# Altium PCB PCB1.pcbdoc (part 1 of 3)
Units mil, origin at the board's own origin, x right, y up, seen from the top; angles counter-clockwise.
Board outline 8664.15 x 6684.89 mil, 2 copper layers (Top Layer, Bottom Layer); 317 components, 306 nets, 1008 pads, 181 vias.
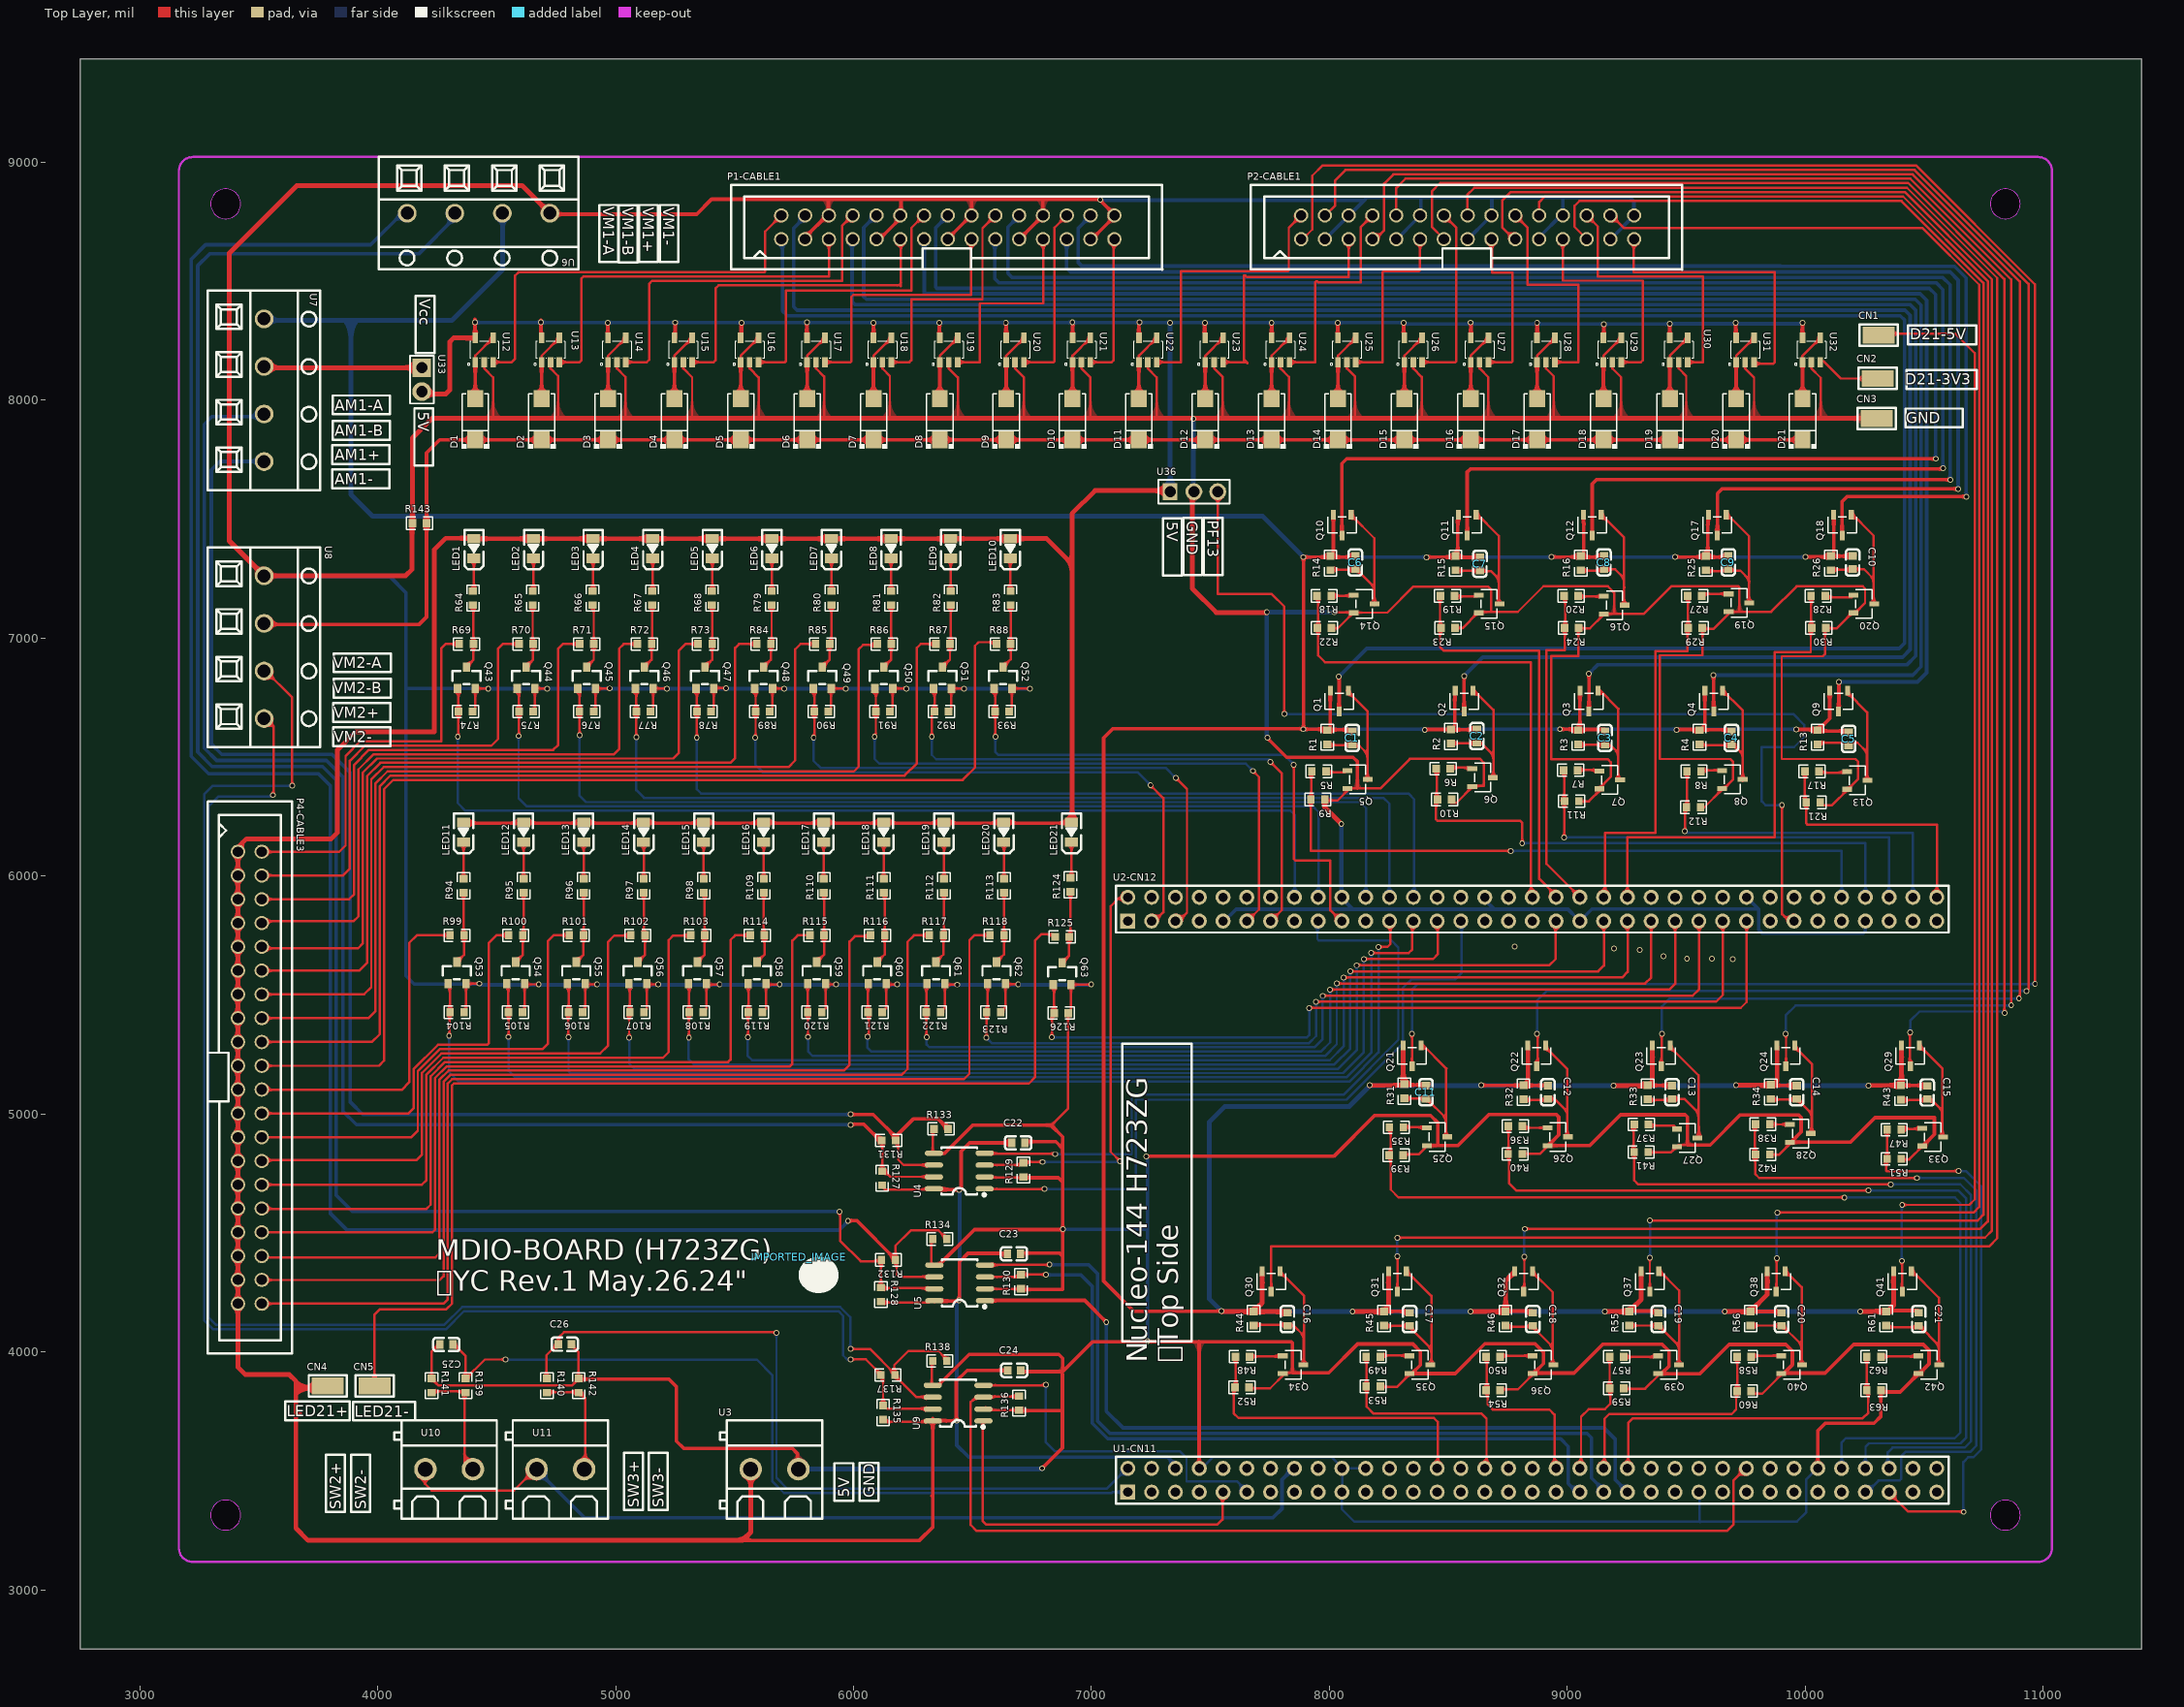
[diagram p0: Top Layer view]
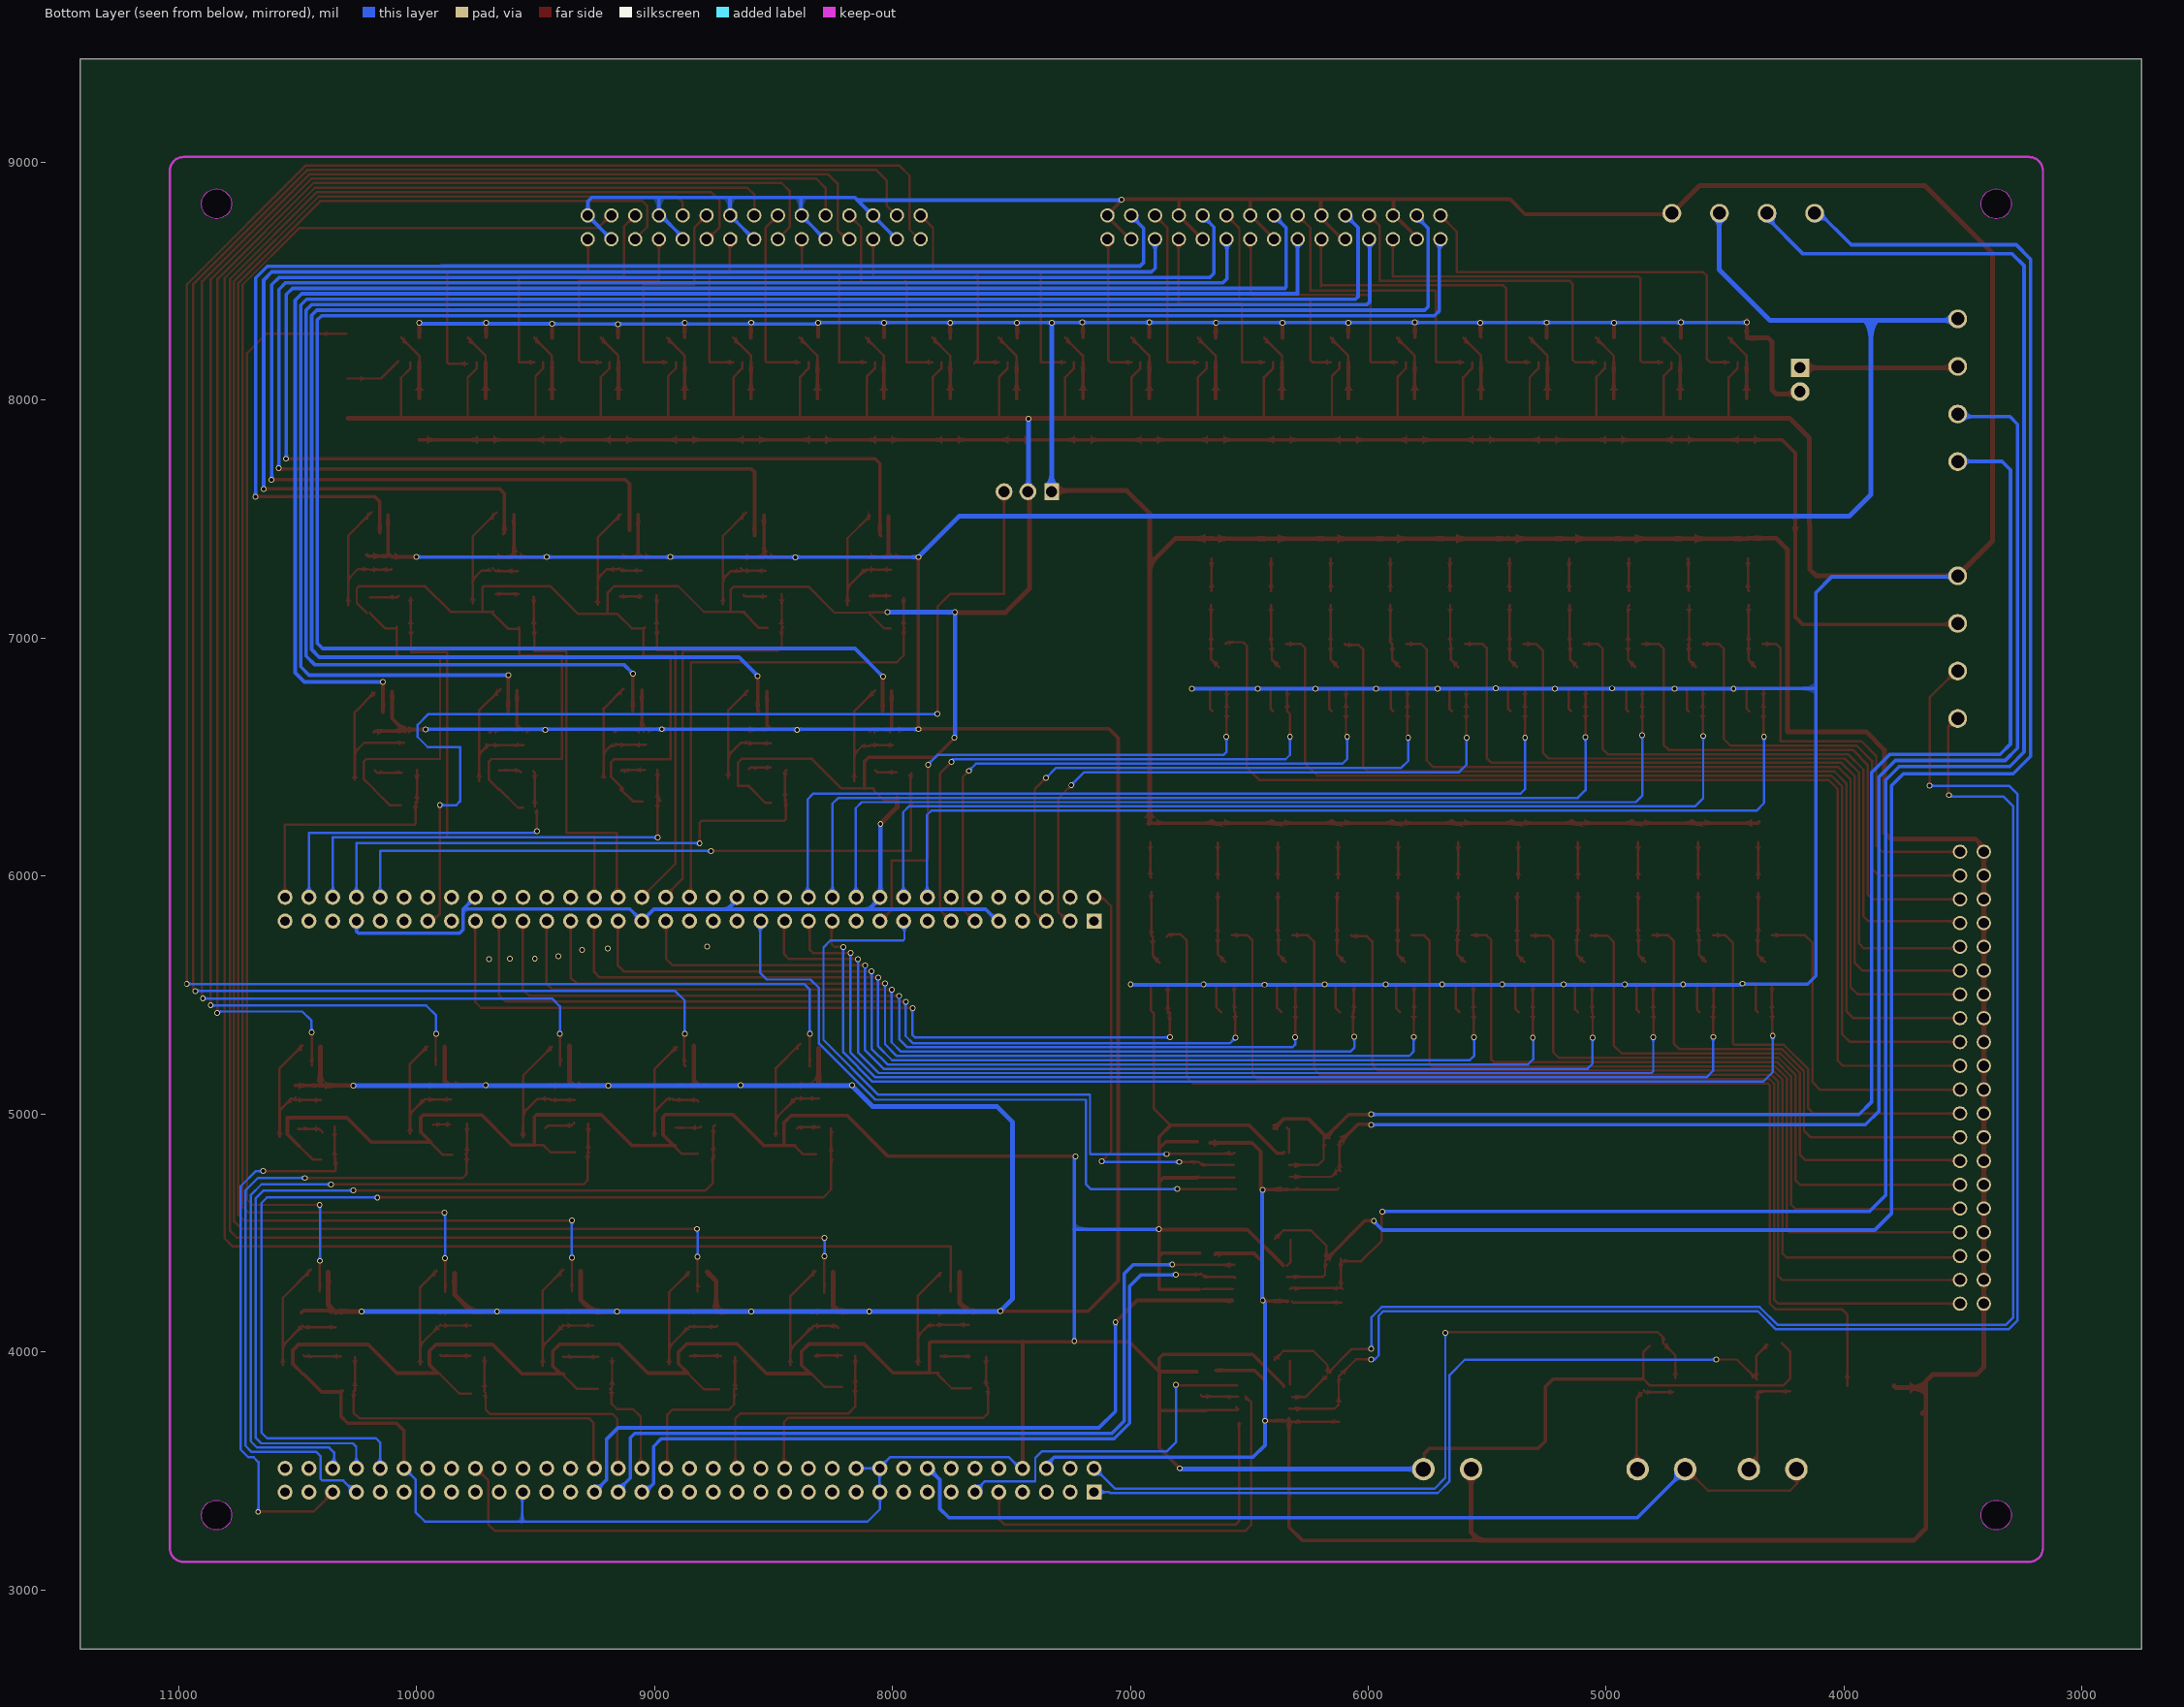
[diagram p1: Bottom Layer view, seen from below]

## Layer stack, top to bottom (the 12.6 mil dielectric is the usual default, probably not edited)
Top Layer: signal copper (thickness not stored)
Dielectric: dielectric 12.6, FR-4, Dk 4.8
Bottom Layer: signal copper (thickness not stored)

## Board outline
11414.15,2750 2750,2750 2750,9434.89 11414.15,9434.89
cut-out: 3424.16,8825.83 ccw(c3361.16,8825.83) 3298.17,8825.83 ccw(c3361.16,8825.83)
cut-out: 10904.47,8825.83 ccw(c10841.48,8825.57) 10778.49,8825.83 ccw(c10841.48,8826.1)
cut-out: 3424.16,3314.02 ccw(c3361.16,3314.02) 3298.17,3314.02 ccw(c3361.16,3314.02)
cut-out: 10904.47,3314.02 ccw(c10841.48,3313.76) 10778.49,3314.02 ccw(c10841.48,3314.28)

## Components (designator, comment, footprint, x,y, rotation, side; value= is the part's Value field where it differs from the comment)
C1 "CC0603KRX7R9BB104" C0603 8096.46,6580.71 r270 top
C2 "CC0603KRX7R9BB104" C0603 8620.56,6588.58 r270 top
C3 "CC0603KRX7R9BB104" C0603 9158.6,6580.71 r270 top
C4 "CC0603KRX7R9BB104" C0603 9690.58,6580.71 r270 top
C5 "CC0603KRX7R9BB104" C0603 10183.18,6576.77 r270 top
C6 "CC0603KRX7R9BB104" C0603 8109.33,7317.96 r270 top
C7 "CC0603KRX7R9BB104" C0603 8633.08,7312.76 r270 top
C8 "CC0603KRX7R9BB104" C0603 9154.54,7318.74 r270 top
C9 "CC0603KRX7R9BB104" C0603 9677.15,7318.74 r270 top
C10 "CC0603KRX7R9BB104" C0603 10199.75,7317.96 r270 top
C11 "CC0603KRX7R9BB104" C0603 8406.25,5091.19 r270 top
C12 "CC0603KRX7R9BB104" C0603 8918.53,5091.19 r270 top
C13 "CC0603KRX7R9BB104" C0603 9440.51,5091.19 r270 top
C14 "CC0603KRX7R9BB104" C0603 9964.56,5091.19 r270 top
C15 "CC0603KRX7R9BB104" C0603 10513.35,5090.23 r270 top
C16 "CC0603KRX7R9BB104" C0603 7824.05,4137.39 r270 top
C17 "CC0603KRX7R9BB104" C0603 8337.81,4137.39 r270 top
C18 "CC0603KRX7R9BB104" C0603 8855.53,4137.39 r270 top
C19 "CC0603KRX7R9BB104" C0603 9383.25,4137.39 r270 top
C20 "CC0603KRX7R9BB104" C0603 9900.97,4137.39 r270 top
C21 "CC0603KRX7R9BB104" C0603 10477.74,4137.39 r270 top
C22 "CC0603KRX7R9BB104" C0603 6692.77,4878.39 r0 top
C23 "CC0603KRX7R9BB104" C0603 6674.79,4412.07 r0 top
C24 "CC0603KRX7R9BB104" C0603 6676.02,3922.29 r0 top
C25 "CC0603KRX7R9BB104" C0603 4288.48,4031.19 r180 top
C26 "CC0603KRX7R9BB104" C0603 4786.68,4032.37 r0 top
CN1 "5017" CONN-SMD_5017 10309.01,8273.69 r0 top
CN2 "5017" CONN-SMD_5017 10305.08,8091.8 r0 top
CN3 "5017" CONN-SMD_5017 10301.14,7923.29 r0 top
CN4 "5017" CONN-SMD_5017 3790.3,3857.33 r0 top
CN5 "5017" CONN-SMD_5017 3987.15,3857.33 r0 top
D1 "B360A-13-F" SMA_L4.4-W2.6-LS5.0-RD 4410.46,7920.32 r90 top
D2 "B360A-13-F" SMA_L4.4-W2.6-LS5.0-RD 4689.39,7920.32 r90 top
D3 "B360A-13-F" SMA_L4.4-W2.6-LS5.0-RD 4968.33,7920.32 r90 top
D4 "B360A-13-F" SMA_L4.4-W2.6-LS5.0-RD 5247.27,7920.32 r90 top
D5 "B360A-13-F" SMA_L4.4-W2.6-LS5.0-RD 5526.2,7920.32 r90 top
D6 "B360A-13-F" SMA_L4.4-W2.6-LS5.0-RD 5805.14,7920.32 r90 top
D7 "B360A-13-F" SMA_L4.4-W2.6-LS5.0-RD 6084.08,7920.32 r90 top
D8 "B360A-13-F" SMA_L4.4-W2.6-LS5.0-RD 6363.02,7920.32 r90 top
D9 "B360A-13-F" SMA_L4.4-W2.6-LS5.0-RD 6641.95,7920.32 r90 top
D10 "B360A-13-F" SMA_L4.4-W2.6-LS5.0-RD 6920.89,7920.32 r90 top
D11 "B360A-13-F" SMA_L4.4-W2.6-LS5.0-RD 7199.83,7920.32 r90 top
D12 "B360A-13-F" SMA_L4.4-W2.6-LS5.0-RD 7478.76,7920.32 r90 top
D13 "B360A-13-F" SMA_L4.4-W2.6-LS5.0-RD 7757.7,7920.32 r90 top
D14 "B360A-13-F" SMA_L4.4-W2.6-LS5.0-RD 8036.64,7920.32 r90 top
D15 "B360A-13-F" SMA_L4.4-W2.6-LS5.0-RD 8315.58,7920.32 r90 top
D16 "B360A-13-F" SMA_L4.4-W2.6-LS5.0-RD 8594.51,7920.32 r90 top
D17 "B360A-13-F" SMA_L4.4-W2.6-LS5.0-RD 8873.45,7920.32 r90 top
D18 "B360A-13-F" SMA_L4.4-W2.6-LS5.0-RD 9152.39,7920.32 r90 top
D19 "B360A-13-F" SMA_L4.4-W2.6-LS5.0-RD 9431.32,7920.32 r90 top
D20 "B360A-13-F" SMA_L4.4-W2.6-LS5.0-RD 9710.26,7920.32 r90 top
D21 "B360A-13-F" SMA_L4.4-W2.6-LS5.0-RD 9989.2,7920.32 r90 top
IMPORTED_IMAGE "IMPORTED_IMAGE" IMPORTED_IMAGE 5770.23,4398.28 r0 top
LED1 "SZYY0805YG" LED0805-R-RD_GREEN 4404.46,7377.01 r90 top
LED2 "SZYY0805YG" LED0805-R-RD_GREEN 4654.99,7377.01 r90 top
LED3 "SZYY0805YG" LED0805-R-RD_GREEN 4905.51,7377.01 r90 top
LED4 "SZYY0805YG" LED0805-R-RD_GREEN 5156.04,7377.01 r90 top
LED5 "SZYY0805YG" LED0805-R-RD_GREEN 5406.56,7377.01 r90 top
LED6 "SZYY0805YG" LED0805-R-RD_GREEN 5657.09,7377.01 r90 top
LED7 "SZYY0805YG" LED0805-R-RD_GREEN 5907.61,7377.01 r90 top
LED8 "SZYY0805YG" LED0805-R-RD_GREEN 6158.14,7377.01 r90 top
LED9 "SZYY0805YG" LED0805-R-RD_GREEN 6408.66,7377.01 r90 top
LED10 "SZYY0805YG" LED0805-R-RD_GREEN 6659.19,7377.01 r90 top
LED11 "SZYY0805YG" LED0805-R-RD_GREEN 4361.16,6184.1 r90 top
LED12 "SZYY0805YG" LED0805-R-RD_GREEN 4613.43,6184.1 r90 top
LED13 "SZYY0805YG" LED0805-R-RD_GREEN 4865.71,6184.1 r90 top
LED14 "SZYY0805YG" LED0805-R-RD_GREEN 5117.98,6184.1 r90 top
LED15 "SZYY0805YG" LED0805-R-RD_GREEN 5370.25,6184.1 r90 top
LED16 "SZYY0805YG" LED0805-R-RD_GREEN 5622.53,6184.1 r90 top
LED17 "SZYY0805YG" LED0805-R-RD_GREEN 5874.8,6184.1 r90 top
LED18 "SZYY0805YG" LED0805-R-RD_GREEN 6127.08,6184.1 r90 top
LED19 "SZYY0805YG" LED0805-R-RD_GREEN 6379.35,6184.1 r90 top
LED20 "SZYY0805YG" LED0805-R-RD_GREEN 6631.63,6184.1 r90 top
LED21 "SZYY0805YG" LED0805-R-RD_GREEN 6916.28,6184.1 r90 top
P1-CABLE1 "2.54-2*15P简牛" IDC-TH_30P-P2.54-V-R2-C15-S2.54 6396.6,8727.41 r0 top
P2-CABLE1 "2.54-2*15P简牛" IDC-TH_30P-P2.54-V-R2-C15-S2.54 8581.63,8727.4 r0 top
P4-CABLE3 "2.54-2*20P直简牛" IDC-TH_40P-P2.54_C9138 3462.95,5152.6 r270 top
Q1 "SI2301CDS-T1-GE3" SOT-23-3_L3.0-W1.7-P0.95-LS2.9-BR 8042.27,6735.28 r90 top
Q2 "SI2301CDS-T1-GE3" SOT-23-3_L3.0-W1.7-P0.95-LS2.9-BR 8566.88,6735.28 r90 top
Q3 "SI2301CDS-T1-GE3" SOT-23-3_L3.0-W1.7-P0.95-LS2.9-BR 9091.48,6735.28 r90 top
Q4 "SI2301CDS-T1-GE3" SOT-23-3_L3.0-W1.7-P0.95-LS2.9-BR 9616.09,6735.28 r90 top
Q5 "S8050 J3Y_C2146" SOT-23-3_L3.0-W1.7-P0.95-LS2.9-BR 8119.11,6406.06 r180 top
Q6 "S8050 J3Y_C2146" SOT-23-3_L3.0-W1.7-P0.95-LS2.9-BR 8644.19,6413.93 r180 top
Q7 "S8050 J3Y_C2146" SOT-23-3_L3.0-W1.7-P0.95-LS2.9-BR 9178.89,6404.14 r180 top
Q8 "S8050 J3Y_C2146" SOT-23-3_L3.0-W1.7-P0.95-LS2.9-BR 9694.36,6406.06 r180 top
Q9 "SI2301CDS-T1-GE3" SOT-23-3_L3.0-W1.7-P0.95-LS2.9-BR 10140.7,6735.28 r90 top
Q10 "SI2301CDS-T1-GE3" SOT-23-3_L3.0-W1.7-P0.95-LS2.9-BR 8054.08,7475.44 r90 top
Q11 "SI2301CDS-T1-GE3" SOT-23-3_L3.0-W1.7-P0.95-LS2.9-BR 8579.67,7475.44 r90 top
Q12 "SI2301CDS-T1-GE3" SOT-23-3_L3.0-W1.7-P0.95-LS2.9-BR 9105.26,7475.44 r90 top
Q13 "S8050 J3Y_C2146" SOT-23-3_L3.0-W1.7-P0.95-LS2.9-BR 10219.44,6402.12 r180 top
Q14 "S8050 J3Y_C2146" SOT-23-3_L3.0-W1.7-P0.95-LS2.9-BR 8146.67,7144.09 r180 top
Q15 "S8050 J3Y_C2146" SOT-23-3_L3.0-W1.7-P0.95-LS2.9-BR 8671.75,7144.09 r180 top
Q16 "S8050 J3Y_C2146" SOT-23-3_L3.0-W1.7-P0.95-LS2.9-BR 9198.11,7138.96 r180 top
Q17 "SI2301CDS-T1-GE3" SOT-23-3_L3.0-W1.7-P0.95-LS2.9-BR 9630.85,7475.44 r90 top
Q18 "SI2301CDS-T1-GE3" SOT-23-3_L3.0-W1.7-P0.95-LS2.9-BR 10156.45,7475.44 r90 top
Q19 "S8050 J3Y_C2146" SOT-23-3_L3.0-W1.7-P0.95-LS2.9-BR 9721.91,7148.67 r180 top
Q20 "S8050 J3Y_C2146" SOT-23-3_L3.0-W1.7-P0.95-LS2.9-BR 10247,7144.09 r180 top
Q21 "SI2301CDS-T1-GE3" SOT-23-3_L3.0-W1.7-P0.95-LS2.9-BR 8347.97,5244.4 r90 top
Q22 "SI2301CDS-T1-GE3" SOT-23-3_L3.0-W1.7-P0.95-LS2.9-BR 8871.59,5244.4 r90 top
Q23 "SI2301CDS-T1-GE3" SOT-23-3_L3.0-W1.7-P0.95-LS2.9-BR 9395.22,5244.4 r90 top
Q24 "SI2301CDS-T1-GE3" SOT-23-3_L3.0-W1.7-P0.95-LS2.9-BR 9918.84,5244.4 r90 top
Q25 "S8050 J3Y_C2146" SOT-23-3_L3.0-W1.7-P0.95-LS2.9-BR 8453.31,4903.93 r180 top
Q26 "S8050 J3Y_C2146" SOT-23-3_L3.0-W1.7-P0.95-LS2.9-BR 8960.72,4903.93 r180 top
Q27 "S8050 J3Y_C2146" SOT-23-3_L3.0-W1.7-P0.95-LS2.9-BR 9504.61,4899.14 r180 top
Q28 "S8050 J3Y_C2146" SOT-23-3_L3.0-W1.7-P0.95-LS2.9-BR 9980.51,4918.34 r180 top
Q29 "SI2301CDS-T1-GE3" SOT-23-3_L3.0-W1.7-P0.95-LS2.9-BR 10442.46,5244.4 r90 top
Q30 "SI2301CDS-T1-GE3" SOT-23-3_L3.0-W1.7-P0.95-LS2.9-BR 7755.56,4295.86 r90 top
Q31 "SI2301CDS-T1-GE3" SOT-23-3_L3.0-W1.7-P0.95-LS2.9-BR 8286.27,4295.86 r90 top
Q32 "SI2301CDS-T1-GE3" SOT-23-3_L3.0-W1.7-P0.95-LS2.9-BR 8816.98,4295.86 r90 top
Q33 "S8050 J3Y_C2146" SOT-23-3_L3.0-W1.7-P0.95-LS2.9-BR 10536.47,4902.96 r180 top
Q34 "S8050 J3Y_C2146" SOT-23-3_L3.0-W1.7-P0.95-LS2.9-BR 7847.68,3945.79 r180 top
Q35 "S8050 J3Y_C2146" SOT-23-3_L3.0-W1.7-P0.95-LS2.9-BR 8380.98,3945.79 r180 top
Q36 "S8050 J3Y_C2146" SOT-23-3_L3.0-W1.7-P0.95-LS2.9-BR 8898.48,3945.79 r180 top
Q37 "SI2301CDS-T1-GE3" SOT-23-3_L3.0-W1.7-P0.95-LS2.9-BR 9347.69,4295.86 r90 top
Q38 "SI2301CDS-T1-GE3" SOT-23-3_L3.0-W1.7-P0.95-LS2.9-BR 9878.4,4295.86 r90 top
Q39 "S8050 J3Y_C2146" SOT-23-3_L3.0-W1.7-P0.95-LS2.9-BR 9425.98,3945.79 r180 top
Q40 "S8050 J3Y_C2146" SOT-23-3_L3.0-W1.7-P0.95-LS2.9-BR 9943.48,3945.79 r180 top
Q41 "SI2301CDS-T1-GE3" SOT-23-3_L3.0-W1.7-P0.95-LS2.9-BR 10409.11,4295.86 r90 top
Q42 "S8050 J3Y_C2146" SOT-23-3_L3.0-W1.7-P0.95-LS2.9-BR 10520.04,3945.79 r180 top
Q43 "Si2302CDS-T1-GE3" SOT-23_L2.9-W1.3-P1.90-LS2.4-BR 4372.97,6833.7 r270 top
Q44 "Si2302CDS-T1-GE3" SOT-23_L2.9-W1.3-P1.90-LS2.4-BR 4623.62,6833.7 r270 top
Q45 "Si2302CDS-T1-GE3" SOT-23_L2.9-W1.3-P1.90-LS2.4-BR 4878.22,6833.7 r270 top
Q46 "Si2302CDS-T1-GE3" SOT-23_L2.9-W1.3-P1.90-LS2.4-BR 5121,6833.7 r270 top
Q47 "Si2302CDS-T1-GE3" SOT-23_L2.9-W1.3-P1.90-LS2.4-BR 5375.59,6833.7 r270 top
Q48 "Si2302CDS-T1-GE3" SOT-23_L2.9-W1.3-P1.90-LS2.4-BR 5622.31,6833.7 r270 top
Q49 "Si2302CDS-T1-GE3" SOT-23_L2.9-W1.3-P1.90-LS2.4-BR 5869.03,6833.7 r270 top
Q50 "Si2302CDS-T1-GE3" SOT-23_L2.9-W1.3-P1.90-LS2.4-BR 6127.56,6833.7 r270 top
Q51 "Si2302CDS-T1-GE3" SOT-23_L2.9-W1.3-P1.90-LS2.4-BR 6374.28,6833.7 r270 top
Q52 "Si2302CDS-T1-GE3" SOT-23_L2.9-W1.3-P1.90-LS2.4-BR 6628.87,6833.7 r270 top
Q53 "Si2302CDS-T1-GE3" SOT-23_L2.9-W1.3-P1.90-LS2.4-BR 4333.6,5593.54 r270 top
Q54 "Si2302CDS-T1-GE3" SOT-23_L2.9-W1.3-P1.90-LS2.4-BR 4580.32,5593.54 r270 top
Q55 "Si2302CDS-T1-GE3" SOT-23_L2.9-W1.3-P1.90-LS2.4-BR 4834.91,5593.54 r270 top
Q56 "Si2302CDS-T1-GE3" SOT-23_L2.9-W1.3-P1.90-LS2.4-BR 5093.44,5593.54 r270 top
Q57 "Si2302CDS-T1-GE3" SOT-23_L2.9-W1.3-P1.90-LS2.4-BR 5344.1,5593.54 r270 top
Q58 "Si2302CDS-T1-GE3" SOT-23_L2.9-W1.3-P1.90-LS2.4-BR 5594.75,5593.54 r270 top
Q59 "Si2302CDS-T1-GE3" SOT-23_L2.9-W1.3-P1.90-LS2.4-BR 5845.41,5593.54 r270 top
Q60 "Si2302CDS-T1-GE3" SOT-23_L2.9-W1.3-P1.90-LS2.4-BR 6100,5593.54 r270 top
Q61 "Si2302CDS-T1-GE3" SOT-23_L2.9-W1.3-P1.90-LS2.4-BR 6346.72,5593.54 r270 top
Q62 "Si2302CDS-T1-GE3" SOT-23_L2.9-W1.3-P1.90-LS2.4-BR 6601.31,5593.54 r270 top
Q63 "Si2302CDS-T1-GE3" SOT-23_L2.9-W1.3-P1.90-LS2.4-BR 6876.92,5589.61 r270 top
R1 "SCR0603J10K" R0603 7991.59,6583.51 r90 top
R2 "SCR0603J10K" R0603 8510.79,6587.45 r90 top
R3 "SCR0603J10K" R0603 9046.3,6583.51 r90 top
R4 "SCR0603J10K" R0603 9556.1,6583.51 r90 top
R5 "SCR0603J10K" R0603 7956.49,6440.14 r180 top
R6 "SCR0603J10K" R0603 8478.41,6451.76 r180 top
R7 "SCR0603J10K" R0603 9014.12,6444.94 r180 top
R8 "SCR0603J10K" R0603 9532.97,6440.14 r180 top
R9 "SCR0603F100K" R0603 7951.72,6321.9 r180 top
R10 "SCR0603F100K" R0603 8484.95,6321.71 r180 top
R11 "SCR0603F100K" R0603 9019.02,6314.89 r180 top
R12 "SCR0603F100K" R0603 9530.75,6289.37 r180 top
R13 "SCR0603J10K" R0603 10052.18,6583.51 r90 top
R14 "SCR0603J10K" R0603 8004.94,7315.77 r90 top
R15 "SCR0603J10K" R0603 8530.84,7315.77 r90 top
R16 "SCR0603J10K" R0603 9056.75,7315.77 r90 top
R17 "SCR0603J10K" R0603 10029.31,6440.14 r180 top
R18 "SCR0603J10K" R0603 7978.12,7178.17 r180 top
R19 "SCR0603J10K" R0603 8497.31,7178.17 r180 top
R20 "SCR0603J10K" R0603 9016.5,7178.17 r180 top
R21 "SCR0603F100K" R0603 10034.4,6310.08 r180 top
R22 "SCR0603F100K" R0603 7979.28,7043.15 r180 top
R23 "SCR0603F100K" R0603 8498.8,7043.15 r180 top
R24 "SCR0603F100K" R0603 9018.33,7043.15 r180 top
R25 "SCR0603J10K" R0603 9582.65,7315.77 r90 top
R26 "SCR0603J10K" R0603 10108.56,7315.77 r90 top
R27 "SCR0603J10K" R0603 9535.69,7178.17 r180 top
R28 "SCR0603J10K" R0603 10054.87,7178.17 r180 top
R29 "SCR0603F100K" R0603 9537.85,7043.15 r180 top
R30 "SCR0603F100K" R0603 10057.38,7043.15 r180 top
R31 "SCR0603J10K" R0603 8315.99,5095.92 r90 top
R32 "SCR0603J10K" R0603 8816.25,5091.43 r90 top
R33 "SCR0603J10K" R0603 9338.52,5092.07 r90 top
R34 "SCR0603J10K" R0603 9855.85,5093.03 r90 top
R35 "SCR0603J10K" R0603 8281.79,4943.77 r180 top
R36 "SCR0603J10K" R0603 8782.2,4948.58 r180 top
R37 "SCR0603J10K" R0603 9311.44,4956.29 r180 top
R38 "SCR0603J10K" R0603 9821.9,4956.75 r180 top
R39 "SCR0603F100K" R0603 8280.72,4827.02 r180 top
R40 "SCR0603F100K" R0603 8781.48,4831.82 r180 top
R41 "100kΩ" R0603 9311,4840.26 r180 top
R42 "SCR0603F100K" R0603 9821.84,4830.08 r180 top
R43 "SCR0603J10K" R0603 10402.63,5090.15 r90 top
R44 "SCR0603J10K" R0603 7682.33,4140.19 r90 top
R45 "SCR0603J10K" R0603 8230.26,4140.19 r90 top
R46 "SCR0603J10K" R0603 8740.48,4140.19 r90 top
R47 "SCR0603J10K" R0603 10374.34,4934.16 r180 top
R48 "SCR0603J10K" R0603 7635.08,3979.87 r180 top
R49 "SCR0603J10K" R0603 8184.7,3979.87 r180 top
R50 "SCR0603J10K" R0603 8688.63,3979.87 r180 top
R51 "SCR0603F100K" R0603 10374.42,4811.42 r180 top
R52 "SCR0603F100K" R0603 7633.52,3850.97 r180 top
R53 "SCR0603F100K" R0603 8184.7,3854.91 r180 top
R54 "SCR0603F100K" R0603 8688.63,3839.16 r180 top
R55 "SCR0603J10K" R0603 9260.7,4140.19 r90 top
R56 "SCR0603J10K" R0603 9770.91,4140.19 r90 top
R57 "SCR0603J10K" R0603 9208.32,3979.87 r180 top
R58 "SCR0603J10K" R0603 9743.75,3979.87 r180 top
R59 "SCR0603F100K" R0603 9208.32,3847.04 r180 top
R60 "SCR0603F100K" R0603 9743.75,3835.23 r180 top
R61 "SCR0603J10K" R0603 10340.19,4140.19 r90 top
R62 "SCR0603J10K" R0603 10289.19,3979.87 r180 top
R63 "100kΩ" R0603 10289.19,3839.16 r180 top
R64 "0603WAF3300T5E" R0603 4400.54,7168.35 r90 top
R65 "0603WAF3300T5E" R0603 4651.63,7168.35 r90 top
R66 "0603WAF3300T5E" R0603 4902.72,7168.35 r90 top
R67 "0603WAF3300T5E" R0603 5153.82,7168.35 r90 top
R68 "0603WAF3300T5E" R0603 5404.91,7168.35 r90 top
R69 "0603WAF3300T5E" R0603 4372.97,6975.43 r0 top
R70 "0603WAF3300T5E" R0603 4623.85,6975.43 r0 top
R71 "0603WAF3300T5E" R0603 4878.68,6975.43 r0 top
R72 "0603WAF3300T5E" R0603 5121.69,6975.43 r0 top
R73 "0603WAF3300T5E" R0603 5376.51,6975.43 r0 top
R74 "SCR0603J10K" R0603 4369.04,6691.97 r180 top
R75 "SCR0603J10K" R0603 4623.62,6691.97 r180 top
R76 "SCR0603J10K" R0603 4878.22,6691.97 r180 top
R77 "SCR0603J10K" R0603 5117.06,6691.97 r180 top
R78 "SCR0603J10K" R0603 5371.66,6691.97 r180 top
R79 "0603WAF3300T5E" R0603 5656.01,7168.35 r90 top
R80 "0603WAF3300T5E" R0603 5907.1,7168.35 r90 top
R81 "0603WAF3300T5E" R0603 6158.19,7168.35 r90 top
R82 "0603WAF3300T5E" R0603 6409.29,7168.35 r90 top
R83 "0603WAF3300T5E" R0603 6660.38,7168.35 r90 top
R84 "0603WAF3300T5E" R0603 5623.46,6975.43 r0 top
R85 "0603WAF3300T5E" R0603 5870.41,6975.43 r0 top
R86 "0603WAF3300T5E" R0603 6129.17,6975.43 r0 top
R87 "0603WAF3300T5E" R0603 6376.12,6975.43 r0 top
R88 "0603WAF3300T5E" R0603 6630.95,6975.43 r0 top
R89 "SCR0603J10K" R0603 5618.38,6691.97 r180 top
R90 "SCR0603J10K" R0603 5865.09,6691.97 r180 top
R91 "SCR0603J10K" R0603 6123.62,6691.97 r180 top
R92 "SCR0603J10K" R0603 6370.34,6691.97 r180 top
R93 "SCR0603J10K" R0603 6624.94,6691.97 r180 top
R94 "0603WAF3300T5E" R0603 4361.17,5959.69 r90 top
R95 "0603WAF3300T5E" R0603 4613.57,5959.69 r90 top
R96 "0603WAF3300T5E" R0603 4865.98,5959.69 r90 top
R97 "0603WAF3300T5E" R0603 5118.38,5959.69 r90 top
R98 "0603WAF3300T5E" R0603 5370.79,5959.69 r90 top
R99 "0603WAF3300T5E" R0603 4333.6,5751.02 r0 top
R100 "0603WAF3300T5E" R0603 4580.55,5751.02 r0 top
R101 "0603WAF3300T5E" R0603 4835.37,5751.02 r0 top
R102 "0603WAF3300T5E" R0603 5094.13,5751.02 r0 top
R103 "0603WAF3300T5E" R0603 5345.02,5751.02 r0 top
R104 "SCR0603J10K" R0603 4333.6,5428.19 r180 top
R105 "SCR0603J10K" R0603 4578.98,5428.19 r180 top
R106 "SCR0603J10K" R0603 4832.24,5428.19 r180 top
R107 "SCR0603J10K" R0603 5089.44,5428.19 r180 top
R108 "SCR0603J10K" R0603 5338.77,5428.19 r180 top
R109 "0603WAF3300T5E" R0603 5623.2,5959.69 r90 top
R110 "0603WAF3300T5E" R0603 5875.6,5959.69 r90 top
R111 "0603WAF3300T5E" R0603 6128.01,5959.69 r90 top
R112 "0603WAF3300T5E" R0603 6380.42,5959.69 r90 top
R113 "0603WAF3300T5E" R0603 6632.82,5959.69 r90 top
R114 "0603WAF3300T5E" R0603 5595.9,5751.02 r0 top
R115 "0603WAF3300T5E" R0603 5846.79,5751.02 r0 top
R116 "0603WAF3300T5E" R0603 6101.61,5751.02 r0 top
R117 "0603WAF3300T5E" R0603 6348.56,5751.02 r0 top
R118 "0603WAF3300T5E" R0603 6603.39,5751.02 r0 top
R119 "SCR0603J10K" R0603 5588.09,5428.19 r180 top
R120 "SCR0603J10K" R0603 5837.41,5428.19 r180 top
R121 "SCR0603J10K" R0603 6090.67,5428.19 r180 top
R122 "SCR0603J10K" R0603 6336.06,5428.19 r180 top
R123 "SCR0603J10K" R0603 6589.32,5428.19 r180 top
R124 "0603WAF3300T5E" R0603 6912.35,5963.63 r90 top
R125 "0603WAF3300T5E" R0603 6877.08,5744.84 r0 top
R126 "SCR0603J10K" R0603 6872.98,5424.26 r180 top
R127 "SCR0603J10K" R0603 6120.52,4729.74 r270 top
R128 "SCR0603J10K" R0603 6114.97,4240.83 r270 top
R129 "SCR0603J10K" R0603 6714.17,4765.02 r90 top
R130 "SCR0603J10K" R0603 6704.5,4295.49 r90 top
R131 "SCR0603J10K" R0603 6148.32,4888.89 r180 top
R132 "SCR0603J10K" R0603 6146.97,4386.83 r180 top
R133 "SCR0603J10K" R0603 6367.68,4937.44 r0 top
R134 "SCR0603J10K" R0603 6362.87,4474.12 r0 top
R135 "SCR0603J10K" R0603 6124.84,3745.13 r270 top
R136 "SCR0603J10K" R0603 6695.7,3784.5 r90 top
R137 "SCR0603J10K" R0603 6144.52,3902.61 r180 top
R138 "SCR0603J10K" R0603 6363.06,3961.66 r0 top
R139 "SCR0603J10K" R0603 4369.03,3858.49 r270 top
R140 "SCR0603J10K" R0603 4711.55,3858.49 r270 top
R141 "SCR0603J10K" R0603 4226.3,3858.49 r270 top
R142 "SCR0603J10K" R0603 4845.41,3858.49 r270 top
R143 "SCR0603J10K" R0603 4176.13,7483.31 r0 top
U1-CN11 "DS1021-2x35SF11-B" HDR-TH_70P-P2.54-V-M-R2-C35-S2.54 8853.3,3460.26 r0 top
U2-CN12 "DS1021-2x35SF11-B" HDR-TH_70P-P2.54-V-M-R2-C35-S2.54 8853.3,5861.27 r0 top
U3 "KF128-5.08-2P-AA" CONN-TH_P5.08_KF128-5.08-2P 5668.25,3506.93 r0 top
U4 "MAX485ESA+T" SOIC-8_L5.0-W4.0-P1.27-LS6.0-BL 6444.74,4760.28 r90 top
U5 "MAX485ESA+T" SOIC-8_L5.0-W4.0-P1.27-LS6.0-BL 6446.45,4290.03 r90 top
U6 "DB127S-5.08-4P-GN" CONN-TH_4P-P5.08_DB127S-5.08-4P-GN 4424.16,8786.46 r180 top
U7 "DB127S-5.08-4P-GN" CONN-TH_4P-P5.08_DB127S-5.08-4P-GN 3522.58,8042.37 r270 top
U8 "DB127S-5.08-4P-GN" CONN-TH_4P-P5.08_DB127S-5.08-4P-GN 3522.58,6962.24 r270 top
U9 "MAX485ESA+T" SOIC-8_L5.0-W4.0-P1.27-LS6.0-BL 6439.8,3784.5 r90 top
U10 "KF128-5.08-2P-AA" CONN-TH_P5.08_KF128-5.08-2P 4300.78,3506.93 r0 top
U11 "KF128-5.08-2P-AA" CONN-TH_P5.08_KF128-5.08-2P 4768.01,3506.93 r0 top
U12 "OPA376AIDBVR" SOT-23-5_L3.0-W1.7-P0.95-LS2.8-BR 4447.78,8211.66 r270 top
U13 "OPA376AIDBVR" SOT-23-5_L3.0-W1.7-P0.95-LS2.8-BR 4726.72,8211.66 r270 top
U14 "OPA376AIDBVR" SOT-23-5_L3.0-W1.7-P0.95-LS2.8-BR 5005.66,8211.66 r270 top
U15 "OPA376AIDBVR" SOT-23-5_L3.0-W1.7-P0.95-LS2.8-BR 5284.59,8211.66 r270 top
U16 "OPA376AIDBVR" SOT-23-5_L3.0-W1.7-P0.95-LS2.8-BR 5563.53,8211.66 r270 top
U17 "OPA376AIDBVR" SOT-23-5_L3.0-W1.7-P0.95-LS2.8-BR 5842.47,8211.66 r270 top
U18 "OPA376AIDBVR" SOT-23-5_L3.0-W1.7-P0.95-LS2.8-BR 6121.4,8211.66 r270 top
U19 "OPA376AIDBVR" SOT-23-5_L3.0-W1.7-P0.95-LS2.8-BR 6400.34,8211.66 r270 top
U20 "OPA376AIDBVR" SOT-23-5_L3.0-W1.7-P0.95-LS2.8-BR 6679.28,8211.66 r270 top
U21 "OPA376AIDBVR" SOT-23-5_L3.0-W1.7-P0.95-LS2.8-BR 6958.22,8211.66 r270 top
U22 "OPA376AIDBVR" SOT-23-5_L3.0-W1.7-P0.95-LS2.8-BR 7237.15,8211.66 r270 top
U23 "OPA376AIDBVR" SOT-23-5_L3.0-W1.7-P0.95-LS2.8-BR 7516.09,8211.66 r270 top
U24 "OPA376AIDBVR" SOT-23-5_L3.0-W1.7-P0.95-LS2.8-BR 7795.03,8211.66 r270 top
U25 "OPA376AIDBVR" SOT-23-5_L3.0-W1.7-P0.95-LS2.8-BR 8073.96,8211.66 r270 top
U26 "OPA376AIDBVR" SOT-23-5_L3.0-W1.7-P0.95-LS2.8-BR 8352.9,8211.66 r270 top
U27 "OPA376AIDBVR" SOT-23-5_L3.0-W1.7-P0.95-LS2.8-BR 8631.84,8211.66 r270 top
U28 "OPA376AIDBVR" SOT-23-5_L3.0-W1.7-P0.95-LS2.8-BR 8910.78,8211.66 r270 top
U29 "OPA376AIDBVR" SOT-23-5_L3.0-W1.7-P0.95-LS2.8-BR 9189.71,8211.66 r270 top
U30 "OPA376AIDBVR" SOT-23-5_L3.0-W1.7-P0.95-LS2.8-BR 9468.65,8211.66 r270 top
U31 "OPA376AIDBVR" SOT-23-5_L3.0-W1.7-P0.95-LS2.8-BR 9747.59,8211.66 r270 top
U32 "OPA376AIDBVR" SOT-23-5_L3.0-W1.7-P0.95-LS2.8-BR 10026.52,8211.66 r270 top
U33 "XDZ254-1-02-Z-2.5-G1" HDR-TH_2P-P2.54-V-M 4185.36,8086.64 r270 top
U36 "XDZ254-1-03-Z-2.5-G1" HDR-TH_3P-P2.54-V-M-1 7431.09,7615.89 r0 top

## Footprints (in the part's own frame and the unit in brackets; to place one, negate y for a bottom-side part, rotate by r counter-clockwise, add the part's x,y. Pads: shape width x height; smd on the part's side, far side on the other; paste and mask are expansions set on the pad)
C0603 [mm]
  rect 0.8x0.9 smd: 1(-0.7,0) 2(0.7,0)
  silkscreen extent -1.41,-0.71 1.39,0.72
CONN-SMD_5017 [mm]
  rect 3.43x1.78 smd: 1(0,0)
  silkscreen extent -2.03,-1.14 2.03,1.14
CONN-TH_4P-P5.08_DB127S-5.08-4P-GN [mm]
  round 2 hole 1.4: 1(7.62,0) 2(2.54,0) 3(-2.54,0) 4(-7.62,0)
  silkscreen extent -10.66,-6.01 10.66,6
CONN-TH_P5.08_KF128-5.08-2P [mm]
  round 2.4 hole 1.6: 1(-2.54,0) 2(2.54,0)
  silkscreen extent -5.84,-5.3 5.08,5.2
HDR-TH_2P-P2.54-V-M [mm]
  rect 2x2 hole 1.2: 1(-1.27,0)
  round 2 hole 1.2: 2(1.27,0)
  silkscreen extent -2.54,-1.27 2.54,1.27
HDR-TH_3P-P2.54-V-M-1 [mm]
  rect 1.575x1.8 hole 1.2: 1(-2.54,0)
  round 1.8 hole 1.2: 2(0,0) 3(2.54,0)
  silkscreen extent -3.81,-1.27 3.81,1.27
HDR-TH_70P-P2.54-V-M-R2-C35-S2.54 [mm]
  rect 1.6x1.6 hole 1: 1(-43.18,-1.27)
  round 1.6 hole 1: 2(-43.18,1.27) 3(-40.64,-1.27) 4(-40.64,1.27) 5(-38.1,-1.27) 6(-38.1,1.27) 7(-35.56,-1.27) 8(-35.56,1.27) 9(-33.02,-1.27) 10(-33.02,1.27) 11(-30.48,-1.27) 12(-30.48,1.27) 13(-27.94,-1.27) 14(-27.94,1.27) 15(-25.4,-1.27) 16(-25.4,1.27) 17(-22.86,-1.27) 18(-22.86,1.27) 19(-20.32,-1.27) 20(-20.32,1.27) 21(-17.78,-1.27) 22(-17.78,1.27) 23(-15.24,-1.27) 24(-15.24,1.27) 25(-12.7,-1.27) 26(-12.7,1.27) 27(-10.16,-1.27) 28(-10.16,1.27) 29(-7.62,-1.27) 30(-7.62,1.27) 31(-5.08,-1.27) 32(-5.08,1.27) 33(-2.54,-1.27) 34(-2.54,1.27) 35(0,-1.27) 36(0,1.27) 37(2.54,-1.27) 38(2.54,1.27) 39(5.08,-1.27) 40(5.08,1.27) 41(7.62,-1.27) 42(7.62,1.27) 43(10.16,-1.27) 44(10.16,1.27) 45(12.7,-1.27) 46(12.7,1.27) 47(15.24,-1.27) 48(15.24,1.27) 49(17.78,-1.27) 50(17.78,1.27) 51(20.32,-1.27) 52(20.32,1.27) 53(22.86,-1.27) 54(22.86,1.27) 55(25.4,-1.27) 56(25.4,1.27) 57(27.94,-1.27) 58(27.94,1.27) 59(30.48,-1.27) 60(30.48,1.27) 61(33.02,-1.27) 62(33.02,1.27) 63(35.56,-1.27) 64(35.56,1.27) 65(38.1,-1.27) 66(38.1,1.27) 67(40.64,-1.27) 68(40.64,1.27) 69(43.18,-1.27) 70(43.18,1.27)
  silkscreen extent -44.45,-2.5 44.45,2.5
IDC-TH_30P-P2.54-V-R2-C15-S2.54 [mil]
  round 60 hole 43.3: 1(-700,-50) 2(-700,50) 3(-600,-50) 4(-600,50) 5(-500,-50) 6(-500,50) 7(-400,-50) 8(-400,50) 9(-300,-50) 10(-300,50) 11(-200,-50) 12(-200,50) 13(-100,-50) 14(-100,50) 15(0,-50) 16(0,50) 17(100,-50) 18(100,50) 19(200,-50) 20(200,50) 21(300,-50) 22(300,50) 23(400,-50) 24(400,50) 25(500,-50) 26(500,50) 27(600,-50) 28(600,50) 29(700,-50) 30(700,50)
  silkscreen extent -911,-178 902,178
IDC-TH_40P-P2.54_C9138 [mil]
  round 60 hole 43.3: 1(-950,-50) 2(-950,50) 3(-850,-50) 4(-850,50) 5(-750,-50) 6(-750,50) 7(-650,-50) 8(-650,50) 9(-550,-50) 10(-550,50) 11(-450,-50) 12(-450,50) 13(-350,-50) 14(-350,50) 15(-250,-50) 16(-250,50) 17(-150,-50) 18(-150,50) 19(-50,-50) 20(-50,50) 21(50,-50) 22(50,50) 23(150,-50) 24(150,50) 25(250,-50) 26(250,50) 27(350,-50) 28(350,50) 29(450,-50) 30(450,50) 31(550,-50) 32(550,50) 33(650,-50) 34(650,50) 35(750,-50) 36(750,50) 37(850,-50) 38(850,50) 39(950,-50) 40(950,50)
  silkscreen extent -1161,-177 1160,178
IMPORTED_IMAGE [mil]
  silkscreen extent 0,-150 166,0
LED0805-R-RD_GREEN [mm]
  rect 1x1.4 smd: 1(1.05,0) 2(-1.05,0)
  silkscreen extent -2.22,-1.04 1.99,1.01
R0603 [mil]
  rect 31.75x34.02 smd: 1(-29.66,0) 2(29.66,0)
  silkscreen extent -55,-26 55,26
SMA_L4.4-W2.6-LS5.0-RD [mm]
  rect 1.8x1.7 smd: 1(-2.192,0) 2(2.192,0)
  silkscreen extent -3.11,-1.48 2.73,1.48
SOIC-8_L5.0-W4.0-P1.27-LS6.0-BL [mil]
  oval 22.38x76.78 smd: 1(-75,-106.5) 2(-25,-106.5) 3(25,-106.5) 4(75,-106.5) 5(75,106.5) 6(25,106.5) 7(-25,106.5) 8(-75,106.5)
  silkscreen extent -106,-111 98,75
SOT-23-3_L3.0-W1.7-P0.95-LS2.9-BR [mil]
  rect 40.85x20.95 smd: 1(43.36,-37.4) 2(43.36,37.4) 3(-43.36,0)
  silkscreen extent -34,-60 34,60
SOT-23-5_L3.0-W1.7-P0.95-LS2.8-BR [mm]
  rect 1.1x0.6 smd: 1(1.3,-0.95) 2(1.3,0) 3(1.3,0.95) 4(-1.3,0.95) 5(-1.3,-0.95)
  silkscreen extent -0.9,-1.78 1.65,1.55
SOT-23_L2.9-W1.3-P1.90-LS2.4-BR [mm]
  rect 1x0.8 smd: 1(1.15,-0.95) 2(1.15,0.95) 3(-1.15,0)
  silkscreen extent -0.7,-1.5 0.7,1.5

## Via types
v1: diameter 24.02, hole 16, Top Layer to Bottom Layer, 181 vias

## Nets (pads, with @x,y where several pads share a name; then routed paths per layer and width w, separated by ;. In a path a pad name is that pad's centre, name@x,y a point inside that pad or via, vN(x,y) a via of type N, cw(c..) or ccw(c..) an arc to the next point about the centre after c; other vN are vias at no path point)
3V3_VDD: U1-CN11.5
5V: U1-CN11.18
5V_USB_STLK: U2-CN12.8
$2N5945: Q5.1 R5.1 | length 93.1
  Top Layer w10: R5.1@7982.6,6436.56 8064.2,6436.56 Q5.1@8072.31,6444.68
$2N6167: C1.2 Q1.1 Q5.3 R1.1 | length 667.9
  Top Layer w10: R1.1@8000.01,6550.57 8092.92,6550.57 C1.2@8098.05,6545.44 ; Q1.1@8073.66,6779.97 8160.16,6693.47 8160.16,6514.43 ; C1.2@8106.55,6546.2 8128.39,6546.2 8160.16,6514.43 ; Q5.3@8160.16,6400.31 8160.16,6492.58 ; Q5.3@8160.8,6407.36 8160.8,6491.94 8160.16,6492.58 ; 8160.16,6492.58 8160.16,6514.43
$2N10326: Q6.1 R6.1 | length 92.7
  Top Layer w10: R6.1@8513.28,6455.73 8597.86,6455.73 Q6.1@8603.63,6449.97
$2N10332: C2.2 Q2.1 Q6.3 R2.1 | length 610.3
  Top Layer w10: R2.1@8510.5,6557.83 8617.73,6557.83 C2.2@8619.68,6559.79 ; Q2.1@8608.07,6779.97 8689.77,6698.27 8689.77,6507.9 ; C2.2@8615.76,6563.71 C2.2@8619.68,6559.79 ; C2.2@8619.86,6559.97 C2.2@8619.68,6559.79 ; Q6.3@8689.77,6410.88 8689.77,6507.9 ; C2.2@8619.68,6559.79 8637.88,6559.79 8689.77,6507.9
$2N10892: Q7.1 R7.1 | length 104.5
  Top Layer w10: R7.1@9040.6,6446.45 9136.08,6446.45 Q7.1@9140.56,6441.96 ; Q7.1@9125.18,6437.8 Q7.1@9127.11,6439.72
$2N10898: C3.2 Q3.1 Q7.3 R3.1 | length 596.8
  Top Layer w10: R3.1@9036.76,6551.54 9156.9,6551.54 C3.2@9162.67,6557.3 ; Q3.1@9130.95,6787.02 9215.53,6702.44 ; C3.2@9167.47,6547.69 9184.5,6547.69 9214.57,6517.62 ; Q7.3@9214.57,6413.13 9214.57,6517.62 ; 9214.57,6702.44 9214.57,6517.62
$2N10920: Q8.1 R8.1 | length 94.9
  Top Layer w10: R8.1@9563.36,6436.92 9571.33,6444.89 Q8.1@9654.95,6444.89
$2N10926: C4.2 Q4.1 Q8.3 R4.1 | length 633.2
  Top Layer w10: R4.1@9550.69,6549.76 C4.2@9701.6,6549.76 ; Q4.1@9647.77,6786.21 9738.12,6695.86 9738.12,6513.24 ; C4.2@9706.4,6554.57 C4.2@9701.6,6549.76 ; Q8.3@9738.12,6399.82 9738.12,6513.24 ; C4.2@9701.6,6549.76 9738.12,6513.24
$2N12024: Q13.1 R17.1 | length 117.3
  Top Layer w10: R17.1@10063.96,6434.42 10165.84,6434.42 Q13.1@10176.74,6445.32
$2N12030: C5.2 Q9.1 Q13.3 R13.1 | length 735.1
  Top Layer w10: R13.1@10053.07,6560.66 10220.45,6560.66 10259.88,6521.23 Q13.3@10259.88,6408.71 ; Q9.1@10178.18,6771.07 10260.84,6688.41 Q13.3@10260.84,6405.83
$2N12052: Q14.1 R18.1 | length 87.8
  Top Layer w10: R18.1@8009.13,7178.19 8092.44,7178.19 Q14.1@8095.64,7174.99
$2N12058: C6.2 Q10.1 Q14.3 R14.1 | length 700.5
  Top Layer w10: R14.1@8006.9,7288.73 8105.9,7288.73 C6.2@8111.67,7282.96 ; Q10.1@8094.68,7514.83 8189.51,7419.99 8189.51,7143.17 Q14.3@8190.8,7141.89 ; C6.2@8114.55,7288.73 8188.56,7214.72 Q14.3@8188.56,7138.78
$2N12080: Q15.1 R19.1 | length 98.1
  Top Layer w10: R19.1@8530.73,7174.99 8619.8,7174.99 Q15.1@8626.21,7181.39
$2N12086: C7.2 Q11.1 Q15.3 R15.1 | length 624
  Top Layer w10: R15.1@8532.67,7282.96 8625.9,7282.96 C7.2@8637.43,7294.49 ; Q11.1@8615.42,7527.64 8713.07,7429.99 ; C7.2@8635.51,7281.04 8680.84,7281.04 8712.4,7249.47 ; Q15.3@8712.4,7143.59 8712.4,7249.47 ; 8712.4,7429.99 8712.4,7249.47
$2N12108: Q16.1 R20.1 | length 92.5
  Top Layer w10: R20.1@9053.61,7174.99 9145.24,7174.99 Q16.1@9145.88,7174.35
$2N12114: C8.2 Q12.1 Q16.3 R16.1 | length 665.5
  Top Layer w10: R16.1@9054.58,7284.56 9139.17,7284.56 C8.2@9149.42,7294.81 ; Q12.1@9142.02,7520.3 9239.44,7422.88 9239.44,7205.65 ; C8.2@9154.21,7289.05 9202.1,7289.05 9239.44,7251.7 9239.44,7205.65 ; Q16.3@9239.44,7141.02 9239.44,7205.65
$2N12680: Q19.1 R27.1 | length 93.2
  Top Layer w10: R27.1@9572.83,7186.27 Q19.1@9666.07,7186.27
$2N12686: C9.2 Q17.1 Q19.3 R25.1 | length 662.1
  Top Layer w10: R25.1@9574.76,7282.39 9668.95,7282.39 C9.2@9680.49,7293.92 ; Q17.1@9665.11,7528.16 9765.07,7428.2 9765.07,7246.68 ; C9.2@9689.14,7284.31 9727.44,7284.31 9765.07,7246.68 ; Q19.3@9765.07,7147.82 9765.07,7208.38 ; 9765.07,7208.38 9765.07,7246.68 ; 9765.07,7208.38 9765.07,7246.68
$2N12708: Q20.1 R28.1 | length 121.6
  Top Layer w10: R28.1@10076.5,7177.68 10082.26,7171.92 Q20.1@10195.68,7171.92
$2N12714: C10.2 Q18.1 Q20.3 R26.1 | length 662.5
  Top Layer w10: R26.1@10107.32,7289.65 10108.6,7288.37 C10.2@10193.82,7288.37 ; Q18.1@10190.88,7528.51 10287.95,7431.43 10287.95,7205.56 ; C10.2@10203.37,7290.14 10246.78,7290.14 10287.95,7248.97 10287.95,7205.56 ; Q20.3@10287.95,7138.27 10287.95,7205.56
$3N9504: Q25.1 R35.1 | length 101
  Top Layer w10: R35.1@8307.56,4944.61 R35.1@8321.37,4944.61 ; R35.1@8320.55,4943.79 R35.1@8321.37,4944.61 ; R35.1@8324.39,4947.64 R35.1@8321.37,4944.61 ; Q25.1@8400.69,4938.63 8394.71,4944.61 R35.1@8321.37,4944.61
$3N9510: C11.2 Q21.1 Q25.3 R31.1 | length 643.7
  Top Layer w10: R31.1@8308.84,5065.08 8403.68,5065.08 C11.2@8404.96,5066.36 ; Q21.1@8387.45,5295.33 8492.11,5190.67 ; C11.2@8409.01,5063.83 8490.71,4982.13 ; Q25.3@8490.71,4907.16 8490.71,4982.13 ; 8490.71,5190.67 8490.71,4982.13
$3N9532: Q26.1 R36.1 | length 110
  Top Layer w10: R36.1@8804.86,4947.71 8810.63,4941.94 Q26.1@8912.52,4941.94
$3N9538: C12.2 Q22.1 Q26.3 R32.1 | length 753.1
  Top Layer w10: R32.1@8815.93,5052.28 8822.32,5058.66 C12.2@8920.95,5058.66 ; Q22.1@8907.38,5281.78 9000.62,5188.54 9000.62,5013.05 ; C12.2@8921.91,5063.99 8945.85,5063.99 8996.79,5013.05 9000.62,5013.05 ; Q26.3@9000.62,4907.88 Q26.3@9000.62,4909.8 ; Q26.3@9000.65,4908.21 Q26.3@9000.65,4909.77 ; 9000.65,4985.24 Q26.3@9000.65,4909.77 ; Q26.3@9002.54,4907.88 Q26.3@9000.65,4909.77 ; Q26.3@9000.62,4909.8 9000.62,4962.67 ; Q26.3@9000.62,4909.8 8999.98,4910.44 8999.98,4962.03 9000.62,4962.67 ; 9000.62,4962.67 9000.62,4985.28 9000.62,5013.05
$3N9560: Q27.1 R37.1 | length 128.8
  Top Layer w10: R37.1@9337.99,4962.56 9349.06,4951.5 9448.01,4951.5 Q27.1@9458.01,4941.5
$3N9566: C13.2 Q23.1 Q27.3 R33.1 | length 715.5
  Top Layer w10: R33.1@9337.22,5058.82 9435.86,5058.82 C13.2@9436.81,5059.78 ; Q23.1@9431.57,5283.1 9551.72,5162.96 9551.72,5005.12 ; C13.2@9437.34,5063.96 9492.88,5063.96 9551.72,5005.12 ; Q27.3@9551.72,4901.52 9551.72,4949.58 ; Q27.3@9554.6,4905.36 9554.6,4946.69 9551.72,4949.58 ; 9551.72,4949.58 9551.72,5005.12
$3N9588: Q28.1 R38.1 | length 72.2
  Top Layer w10: R38.1@9859.65,4956.16 9928.85,4956.16 Q28.1@9930.99,4954.02
$3N9594: C14.2 Q24.1 Q28.3 R34.1 | length 668.7
  Top Layer w10: R34.1@9855.96,5060.87 9958.49,5060.87 C14.2@9959.77,5062.15 ; Q24.1@9955.23,5283.92 10028.28,5210.87 Q28.3@10028.28,4917.71 ; C14.2@9966.76,5061.89 10026.36,5002.29 Q28.3@10026.36,4918.67
$3N9616: Q33.1 R47.1 | length 108.8
  Top Layer w10: R47.1@10395.16,4922.32 10410.54,4937.69 10497.24,4937.69 Q33.1@10497.49,4937.95
$3N9622: C15.2 Q29.1 Q33.3 R43.1 | length 732.6
  Top Layer w10: R43.1@10402.29,5058.19 10510.03,5058.19 C15.2@10514.34,5062.5 ; Q29.1@10479.74,5287.56 10577.3,5190 Q33.3@10577.3,4905.01 ; C15.2@10509.06,5069.38 C15.2@10518.67,5059.76 ; C15.2@10525.4,5065.53 10575.38,5015.55 Q33.3@10575.38,4904.05
$3N9644: Q34.1 R48.1 | length 124.2
  Top Layer w10: R48.1@7676.16,3981.18 7796.31,3981.18 Q34.1@7799.19,3984.07
$3N9650: C16.2 Q30.1 Q34.3 R44.1 | length 766.7
  Top Layer w10: R44.1@7680.29,4114.29 7812.29,4114.29 C16.2@7815.49,4111.08 ; Q30.1@7796.91,4332.79 7893.03,4236.68 Q34.3@7893.03,3947.68 ; C16.2@7826.39,4111.08 7849.37,4111.08 7891.75,4068.71 Q34.3@7891.75,3946.4
$3N9672: Q35.1 R49.1 | length 114.4
  Top Layer w10: R49.1@8213.58,3984.53 8322.51,3984.53 Q35.1@8326.36,3980.68
$3N9678: C17.2 Q31.1 Q35.3 R45.1 | length 747.8
  Top Layer w10: R45.1@8228.96,4101.15 8236.65,4108.84 8332.76,4108.84 8428.88,4012.72 ; Q31.1@8324.43,4339.52 8428.88,4235.07 8428.88,4012.72 ; Q35.3@8428.88,3944.16 8428.88,4012.72 ; Q35.3@8429.52,3946.72 8429.52,4012.08 8428.88,4012.72
$3N9700: Q36.1 R50.1 | length 130.2
  Top Layer w10: R50.1@8721.72,3983.73 8849.24,3983.73 Q36.1@8851.16,3981.8
$3N9706: C18.2 Q32.1 Q36.3 R46.1 | length 666.1
  Top Layer w10: R46.1@8737.1,4109.32 8740.94,4105.48 C18.2@8854.36,4105.48 ; C18.2@8851.16,4108.68 C18.2@8854.36,4105.48 ; Q32.1@8855,4334.88 8938.95,4250.93 8938.95,4020.89 ; C18.2@8855.64,4105.48 C18.2@8854.36,4105.48 ; Q36.3@8938.95,3947.84 8938.95,4020.89 ; C18.2@8854.36,4105.48 8938.95,4020.89
$3N9728: Q39.1 R57.1 | length 148
  Top Layer w10: R57.1@9236.91,3978.92 Q39.1@9384.93,3978.92
$3N9734: C19.2 Q37.1 Q39.3 R55.1 | length 771.9
  Top Layer w10: R55.1@9259.02,4110.6 C19.2@9384.93,4110.6 ; Q37.1@9382.26,4346.3 9470.26,4258.3 Q39.3@9470.26,3944.75 ; C19.2@9386.85,4112.52 C19.2@9384.93,4110.6 ; Q39.3@9469.83,3940.47 9469.83,4025.7 C19.2@9384.93,4110.6
$3N9756: Q40.1 R58.1 | length 128.5
  Top Layer w10: R58.1@9773.93,3983.59 9896.96,3983.59 Q40.1@9900.8,3987.43
$3N9762: C20.2 Q38.1 Q40.3 R56.1 | length 754.8
  Top Layer w10: R56.1@9772.07,4110.71 C20.2@9902.15,4110.71 ; C20.2@9900.87,4113.91 9984.81,4029.97 Q40.3@9984.81,3946.03 ; Q38.1@9916.25,4341.39 9985.45,4272.19 Q40.3@9985.45,3947.95
$4N2136: Q42.1 R62.1 | length 159.1
  Top Layer w10: R62.1@10318.91,3980.7 10469.82,3980.7 Q42.1@10475.58,3986.47
$4N2142: C21.2 Q41.1 Q42.3 R61.1 | length 789.3
  Top Layer w10: R61.1@10339.8,4103.66 10473.09,4103.66 10479.49,4110.07 10562.16,4027.41 Q42.3@10562.16,3944.75 ; Q41.1@10444.89,4345.24 10562.8,4227.33 Q42.3@10562.8,3946.67
$5N840: LED1.2 R64.2 | length 139.3
  Top Layer w10: R64.2@4400.54,7198.01 4404.46,7201.93 LED1.2@4404.46,7335.66
$5N2616: Q43.3 R64.1 R69.2 | length 272.9
  Top Layer w10: Q43.3@4372.97,6878.98 4402.63,6908.64 R69.2@4402.63,6975.43 4402.63,7136.6 R64.1@4400.54,7138.69
$5N3452: LED2.2 R65.2 | length 143.4
  Top Layer w10: R65.2@4651.63,7198.01 4654.99,7201.37 LED2.2@4654.99,7335.66 LED2.2@4658.09,7332.56
$5N3453: Q44.3 R65.1 R70.2 | length 278.4
  Top Layer w10: Q44.3@4623.63,6878.98 4653.51,6908.87 R70.2@4653.51,6975.43 ; R65.1@4651.63,7138.69 4651.63,6977.32 R70.2@4653.51,6975.43 ; R70.2@4657.45,6971.5 R70.2@4653.51,6975.43
$5N3682: LED3.2 R66.2 | length 138.8
  Top Layer w10: R66.2@4902.72,7198.01 4905.51,7200.8 LED3.2@4905.51,7335.66
$5N3683: Q45.3 R66.1 R71.2 | length 274.5
  Top Layer w10: Q45.3@4878.22,6878.98 4908.34,6909.1 R71.2@4908.34,6975.43 4908.34,7133.07 R66.1@4902.72,7138.69
$5N3912: LED4.2 R67.2 | length 138.6
  Top Layer w10: R67.2@5153.82,7198.01 5156.04,7200.23 LED4.2@5156.04,7335.66
$5N3913: Q46.3 R67.1 R72.2 | length 273.3
  Top Layer w10: Q46.3@5121,6878.98 5151.35,6909.33 R72.2@5151.35,6975.43 5153.82,6977.9 R67.1@5153.82,7138.69
$5N5023: LED5.2 R68.2 | length 138.3
  Top Layer w10: R68.2@5404.91,7198.01 5406.56,7199.66 LED5.2@5406.56,7335.66
$5N5024: Q47.3 R68.1 R73.2 | length 272.9
  Top Layer w10: Q47.3@5375.6,6878.98 5406.17,6909.56 R73.2@5406.17,6975.43 5406.17,7137.43 R68.1@5404.91,7138.69
$5N6615: LED6.2 R79.2 | length 138.1
  Top Layer w10: R79.2@5656.01,7198.01 5657.09,7199.09 LED6.2@5657.09,7335.66
$5N6616: Q48.3 R79.1 R84.2 | length 273.7
  Top Layer w10: Q48.3@5622.31,6878.98 5653.12,6909.79 R84.2@5653.12,6975.43 5656.01,6978.32 R79.1@5656.01,7138.69
$5N6624: LED7.2 R80.2 | length 137.9
  Top Layer w10: R80.2@5907.1,7198.01 5907.61,7198.52 LED7.2@5907.61,7335.66
$5N6625: Q49.3 R80.1 R85.2 | length 275.5
  Top Layer w10: Q49.3@5869.03,6878.98 5900.07,6910.02 R85.2@5900.07,6975.43 5907.1,6982.46 R80.1@5907.1,7138.69
$5N6633: LED8.2 R81.2 | length 137.6
  Top Layer w10: R81.2@6158.14,7198.06 LED8.2@6158.14,7335.66
$5N6634: Q50.3 R81.1 R86.2 | length 272.9
  Top Layer w10: Q50.3@6127.56,6878.98 6158.83,6910.25 R86.2@6158.83,6975.43 6158.83,7138.05 R81.1@6158.19,7138.69
$5N6642: LED9.2 R82.2 | length 137.9
  Top Layer w10: LED9.2@6408.66,7335.66 6408.66,7198.63 R82.2@6409.29,7198.01
$5N6643: Q51.3 R82.1 R87.2 | length 274.2
  Top Layer w10: Q51.3@6374.28,6878.98 6405.78,6910.48 R87.2@6405.78,6975.43 6409.29,6978.94 R82.1@6409.29,7138.69
$5N6651: LED10.2 R83.2 | length 138.1
  Top Layer w10: LED10.2@6659.19,7335.66 6659.19,7199.2 R83.2@6660.38,7198.01
$5N6652: Q52.3 R83.1 R88.2 | length 272.9
  Top Layer w10: Q52.3@6628.88,6878.98 6660.61,6910.71 R88.2@6660.61,6975.43 6660.61,7138.46 R83.1@6660.38,7138.69
$6N2659: LED11.2 R94.2 | length 153.4
  Top Layer w10: R94.2@4361.17,5989.35 LED11.2@4361.16,6142.75
$6N2660: Q53.3 R94.1 R99.2 | length 304.4
  Top Layer w10: Q53.3@4333.6,5638.82 4363.26,5668.48 R99.2@4363.26,5751.02 4361.17,5753.12 R94.1@4361.17,5930.03
$6N2668: LED12.2 R95.2 | length 153.5
  Top Layer w10: LED12.2@4613.43,6142.75 4613.43,5989.49 R95.2@4613.57,5989.35
$6N2669: Q54.3 R95.1 R100.2 | length 305
  Top Layer w10: Q54.3@4580.32,5638.82 4610.21,5668.71 R100.2@4610.21,5751.02 4613.57,5754.39 R95.1@4613.57,5930.03
$6N2677: LED13.2 R96.2 | length 153.5
  Top Layer w10: LED13.2@4865.71,6142.75 4865.71,5989.62 R96.2@4865.98,5989.35
$6N2678: Q55.3 R96.1 R101.2 | length 304.1
  Top Layer w10: Q55.3@4834.91,5638.82 4865.03,5668.94 R101.2@4865.03,5751.02 4865.98,5751.97 R96.1@4865.98,5930.03
$6N2686: LED14.2 R97.2 | length 153
  Top Layer w10: R97.2@5118.38,5989.35 LED14.2@5118.38,6142.34
$6N2687: Q56.3 R97.1 R102.2 | length 306
  Top Layer w10: Q56.3@5093.44,5638.82 5123.79,5669.17 R102.2@5123.79,5751.02 5118.38,5756.43 R97.1@5118.38,5930.03
$6N2695: LED15.2 R98.2 | length 153.6
  Top Layer w10: LED15.2@5370.25,6142.75 5370.25,5989.88 R98.2@5370.79,5989.35
$6N2696: Q57.3 R98.1 R103.2 | length 305.5
  Top Layer w10: Q57.3@5344.1,5638.82 5374.68,5669.4 R103.2@5374.68,5751.02 5374.68,5926.14 R98.1@5370.79,5930.03
$6N2704: LED16.2 R109.2 | length 153.7
  Top Layer w10: LED16.2@5622.53,6142.75 5622.53,5990.01 R109.2@5623.2,5989.35
$6N2705: Q58.3 R109.1 R114.2 | length 304.9
  Top Layer w10: Q58.3@5594.76,5638.82 5625.56,5669.63 R114.2@5625.56,5751.02 5623.2,5753.39 R109.1@5623.2,5930.03
$6N2713: LED17.2 R110.2 | length 153.7
  Top Layer w10: LED17.2@5874.8,6142.75 5874.8,5990.15 R110.2@5875.6,5989.35
$6N2714: Q59.3 R110.1 R115.2 | length 304.4
  Top Layer w10: Q59.3@5845.41,5638.82 5876.45,5669.86 R115.2@5876.45,5751.02 5876.45,5929.18 R110.1@5875.6,5930.03
$6N2722: LED18.2 R111.2 | length 153.8
  Top Layer w10: LED18.2@6127.08,6142.75 6127.08,5990.28 R111.2@6128.01,5989.35
$6N2723: Q60.3 R111.1 R116.2 | length 305.5
  Top Layer w10: Q60.3@6100,5638.82 6131.27,5670.09 R116.2@6131.27,5751.02 6131.27,5926.76 R111.1@6128.01,5930.03
$6N2731: LED19.2 R112.2 | length 152.3
  Top Layer w10: R112.2@6380.42,5989.35 LED19.2@6380.42,6141.68
$6N2732: Q61.3 R112.1 R117.2 | length 305.2
  Top Layer w10: Q61.3@6346.72,5638.82 6378.22,5670.32 R117.2@6378.22,5751.02 6380.42,5753.22 R112.1@6380.42,5930.03
$6N2740: LED20.2 R113.2 | length 152.2
  Top Layer w10: R113.2@6632.82,5989.35 LED20.2@6632.82,6141.55
$6N2741: Q62.3 R113.1 R118.2 | length 304.4
  Top Layer w10: Q62.3@6601.32,5638.82 6633.05,5670.55 R118.2@6633.05,5751.02 6632.82,5751.25 R113.1@6632.82,5930.03
$7N461: LED21.2 R124.2 | length 151.1
  Top Layer w10: R124.2@6912.35,5993.29 6916.28,5997.22 LED21.2@6916.28,6142.75
$7N462: Q63.3 R124.1 R125.2 | length 313.8
  Top Layer w10: Q63.3@6876.92,5634.89 6906.74,5664.71 R125.2@6906.74,5744.84 6912.35,5750.45 R124.1@6912.35,5933.97
$9N307: D1.2 U12.1 U12.4 | length 287.2
  Top Layer w10: D1.2@4410.38,8006.71 D1.2@4410.46,8006.64 ; U12.1@4410.38,8160.48 4410.38,8188.05 U12.4@4485.18,8262.85
  Top Layer w15: D1.2@4410.38,8006.71 U12.1@4410.38,8160.48
$9N2603: D2.2 U13.1 U13.4 | length 287.2
  Top Layer w10: D2.2@4689.32,8006.71 D2.2@4689.39,8006.64 ; U13.1@4689.32,8160.48 4689.32,8187.13 4764.12,8261.93 U13.4@4764.12,8262.85
  Top Layer w15: D2.2@4689.32,8006.71 U13.1@4689.32,8160.48
$9N2685: D3.2 U14.1 U14.4 | length 287.2
  Top Layer w10: U14.1@4968.26,8160.48 4968.26,8187.13 5043.06,8261.93 U14.4@5043.06,8262.85
  Top Layer w15: U14.1@4968.26,8160.48 4968.33,8160.4 D3.2@4968.33,8006.64
$9N2767: D4.2 U15.1 U15.4 | length 287.2
  Top Layer w10: U15.1@5247.19,8160.48 5247.19,8188.05 U15.4@5321.99,8262.85
  Top Layer w15: U15.1@5247.19,8160.48 5247.19,8006.71 D4.2@5247.27,8006.64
